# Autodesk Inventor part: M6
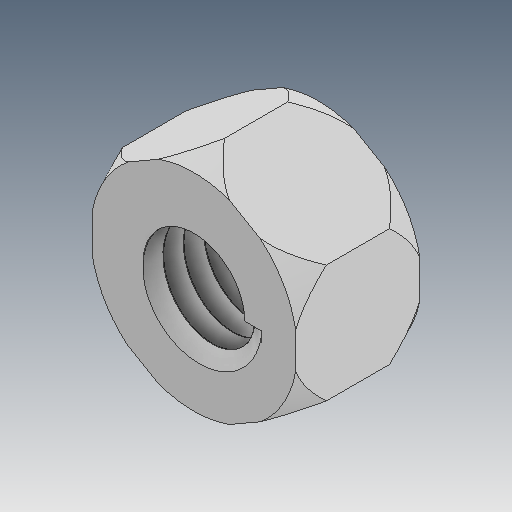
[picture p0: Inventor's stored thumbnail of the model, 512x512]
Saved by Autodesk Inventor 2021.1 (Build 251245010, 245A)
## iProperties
Created: 2019-04
Part Number: M6
Material: Ogólny
Document SubType Name: Modeling
Designer: user
Density: 1 g/cm^3
Appearance: Domyślna
Author: user
Revision Number: ÈÎºÎ
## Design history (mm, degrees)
feature "ÊäÈë1"
node "Bryła1"
